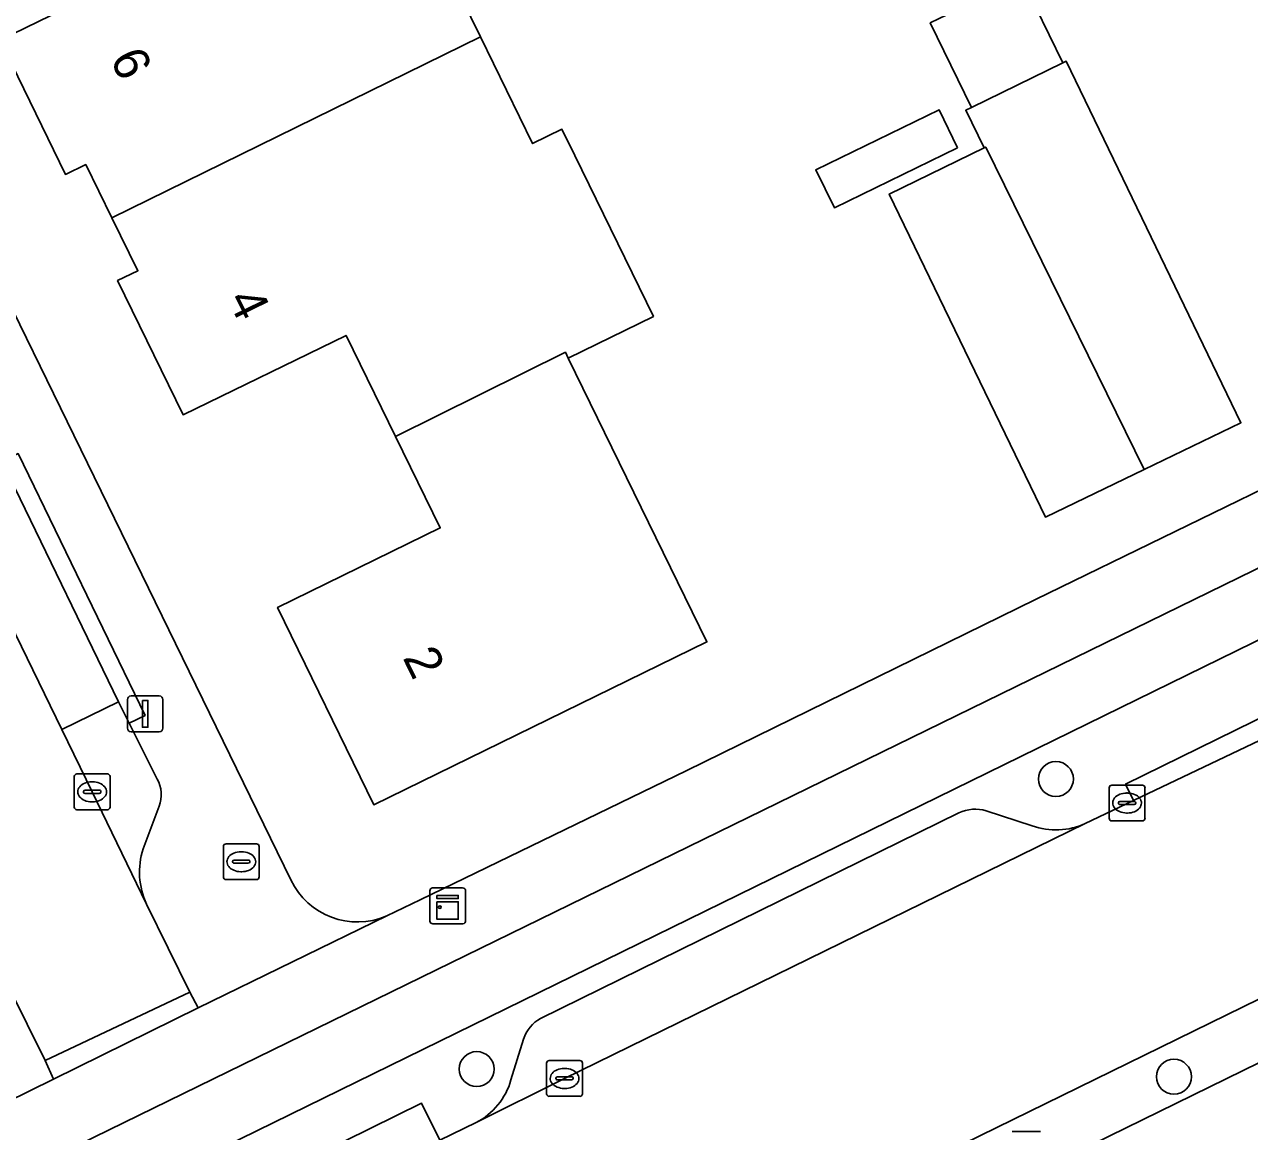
# Model space of a CAD drawing. Extents: x 160455 to 162082, y 388339 to 389736.
# Drawn here: x 160872.78 to 160907, y 388896.44 to 388927.38 of the extents above; entities that cross this region are included whole.
import ezdxf

# ---------------------------------------------------------------- set-up
doc = ezdxf.new("R2010")
doc.units = 0
for name, color, linetype in [('IMGEO_Berm_groen', 7, 'Continuous'), ('IMGEO_Boom', 7, 'Continuous'), ('IMGEO_Brandkraan', 7, 'Continuous'), ('IMGEO_Erf', 7, 'Continuous'), ('IMGEO_Fietspad_gesloten', 7, 'Continuous'), ('IMGEO_Fietspad_open', 7, 'Continuous'), ('IMGEO_Kast', 7, 'Continuous'), ('IMGEO_Kolk', 7, 'Continuous'), ('IMGEO_Lichtmast', 7, 'Continuous'), ('IMGEO_Muur', 7, 'Continuous'), ('IMGEO_Pand', 7, 'Continuous'), ('IMGEO_Pand_nummerreeks', 7, 'Continuous'), ('IMGEO_Parkeervlak_open', 7, 'Continuous'), ('IMGEO_Rijbaan_lokaal_gesloten', 7, 'Continuous'), ('IMGEO_Verkeerseiland_gesloten', 7, 'Continuous'), ('IMGEO_Verkeerseiland_open', 7, 'Continuous'), ('IMGEO_Voetpad_open', 7, 'Continuous')]:
    doc.layers.add(name, color=color, linetype=linetype)

msp = doc.modelspace()

# ---------------------------------------------------------------- linework, layer by layer
at = {"layer": 'IMGEO_Berm_groen'}
msp.add_lwpolyline([(160933.95, 388912.479), (160933.737, 388912.923), (160930.826, 388911.666), (160928.839, 388910.666), (160907.741, 388900.373), (160888.442, 388890.921), (160887.468, 388890.458), (160888.134, 388888.983), (160932.517, 388910.743)], dxfattribs=at)
at = {"layer": 'IMGEO_Boom'}
for centre in [(160901.595, 388906.294), (160885.419, 388898.187), (160904.893, 388897.975)]:
    msp.add_circle(centre, 0.489, dxfattribs=at)
at = {"layer": 'IMGEO_Brandkraan'}
for p, q in [((160878.34, 388903.558), (160878.34, 388904.41)), ((160878.415, 388904.484), (160879.267, 388904.484)), ((160879.341, 388904.41), (160879.341, 388903.558)), ((160878.642, 388904.027), (160879.04, 388904.027)), ((160878.828, 388904.264), (160878.853, 388904.264)), ((160878.599, 388903.978), (160878.599, 388903.99)), ((160879.037, 388903.941), (160878.639, 388903.941)), ((160878.851, 388903.704), (160878.826, 388903.704)), ((160879.083, 388903.99), (160879.083, 388903.978)), ((160879.267, 388903.484), (160878.415, 388903.484))]:
    msp.add_line(p, q, dxfattribs=at)
for points in [[(160878.34, 388903.558), (160878.34, 388904.41)], [(160878.415, 388904.484), (160879.267, 388904.484)], [(160879.341, 388904.41), (160879.341, 388903.558)], [(160879.267, 388903.484), (160878.415, 388903.484)]]:
    msp.add_lwpolyline(points, dxfattribs=at)
for centre, radius, start, end in [((160878.417, 388904.408), 0.0765, 91.552, 178.448), ((160878.417, 388904.408), 0.0765, 91.552, 178.448), ((160879.265, 388904.408), 0.0765, 1.552, 88.448), ((160879.265, 388904.408), 0.0765, 1.552, 88.448), ((160878.639, 388903.987), 0.0403, 85.8775, 175.7526), ((160879.044, 388903.989), 0.0386, 1.7309, 96.639), ((160878.636, 388903.977), 0.0366, 178.938, 274.7102), ((160879.04, 388903.984), 0.043, 264.8664, 352.4533), ((160878.417, 388903.56), 0.0765, 181.552, 268.448), ((160878.417, 388903.56), 0.0765, 181.552, 268.448), ((160879.265, 388903.56), 0.0765, 271.552, 358.448), ((160879.265, 388903.56), 0.0765, 271.552, 358.448)]:
    msp.add_arc(centre, radius, start, end, dxfattribs=at)
for centre, major_axis, ratio, start_param, end_param in [((160878.827, 388903.984), (-0.387, 0.002), 0.722429, 4.712389, 7.853982), ((160878.852, 388903.984), (-0.39, 0.002), 0.717154, 1.570796, 4.712389)]:
    msp.add_ellipse(centre, major_axis=major_axis, ratio=ratio, start_param=start_param, end_param=end_param, dxfattribs=at)
at = {"layer": 'IMGEO_Erf'}
for points in [[(160836.379, 388993.364), (160850.87, 388963.642), (160880.226, 388903.473)], [(160883.115, 388931.96), (160885.523, 388927.033), (160886.979, 388924.053), (160887.797, 388924.452), (160888.157, 388923.716), (160890.351, 388919.223), (160887.97, 388918.059), (160891.847, 388910.126), (160882.539, 388905.576), (160879.852, 388911.09), (160884.4, 388913.312), (160883.151, 388915.868), (160881.77, 388918.694), (160877.216, 388916.477), (160875.386, 388920.224), (160875.952, 388920.5), (160875.226, 388921.978), (160874.494, 388923.466), (160873.928, 388923.19), (160872.1, 388926.948), (160876.717, 388929.199)], [(160882.906, 388902.468), (160883.834, 388902.918), (160891.286, 388906.53), (160901.022, 388911.309), (160908.826, 388915.117), (160918.922, 388920.047), (160928.435, 388924.714)]]:
    msp.add_lwpolyline(points, dxfattribs=at)
for points in [[(160899.592, 388923.932), (160899.078, 388924.987), (160899.236, 388925.064), (160898.086, 388927.425), (160900.641, 388928.67), (160901.791, 388926.309), (160901.886, 388926.355), (160906.766, 388916.253), (160904.061, 388914.947), (160901.301, 388913.614), (160896.94, 388922.64)], [(160898.851, 388923.935), (160895.408, 388922.258), (160894.889, 388923.322), (160898.332, 388925)]]:
    msp.add_lwpolyline(points, close=True, dxfattribs=at)
msp.add_arc((160882.089, 388904.365), 2.066, 205.5909, 293.297, dxfattribs=at)
at = {"layer": 'IMGEO_Fietspad_gesloten'}
for points in [[(160935.958, 388926.245), (160935.472, 388926.041), (160929.623, 388923.115), (160929.542, 388923.081), (160924.149, 388920.448), (160820.314, 388869.678), (160812.524, 388865.895), (160804.151, 388861.828), (160752.018, 388836.29), (160739.38, 388830.051), (160696.889, 388809.242), (160688.114, 388804.953), (160688.97, 388803.215), (160707.492, 388812.318), (160716.69, 388816.833), (160716.639, 388816.936), (160723.758, 388820.418), (160723.804, 388820.325), (160740.999, 388828.766), (160761.388, 388838.743), (160804.958, 388860.084), (160820.353, 388867.581)], [(160820.353, 388867.581), (160909.887, 388911.468), (160925.131, 388918.94), (160926.09, 388919.406), (160929.273, 388920.954), (160932.035, 388922.279)]]:
    msp.add_lwpolyline(points, dxfattribs=at)
at = {"layer": 'IMGEO_Fietspad_open'}
msp.add_lwpolyline([(160936.65, 388912.778), (160936.045, 388912.477), (160933.62, 388911.27), (160933.39, 388911.155), (160932.517, 388910.743), (160888.134, 388888.983), (160875.412, 388882.733), (160870.367, 388880.302), (160868.27, 388879.237), (160861.035, 388875.725), (160851.6, 388871.082), (160844.374, 388867.53), (160835.881, 388863.365), (160828.618, 388859.824), (160821.23, 388856.204)], dxfattribs=at)
at = {"layer": 'IMGEO_Kast'}
for p, q in [((160884.108, 388902.325), (160884.108, 388903.166)), ((160884.108, 388903.166), (160884.108, 388902.325)), ((160884.183, 388903.25), (160885.024, 388903.25)), ((160885.024, 388903.25), (160884.183, 388903.25)), ((160885.108, 388903.175), (160885.108, 388902.334)), ((160885.108, 388902.334), (160885.108, 388903.175)), ((160885.033, 388902.25), (160884.192, 388902.25)), ((160884.192, 388902.25), (160885.033, 388902.25))]:
    msp.add_line(p, q, dxfattribs=at)
for points in [[(160884.303, 388903.04), (160884.903, 388903.04), (160884.903, 388902.955), (160884.303, 388902.955), (160884.303, 388903.04)], [(160884.303, 388902.865), (160884.903, 388902.865), (160884.903, 388902.376), (160884.303, 388902.376), (160884.303, 388902.865)]]:
    msp.add_lwpolyline(points, dxfattribs=at)
msp.add_circle((160884.387, 388902.714), 0.0377, dxfattribs=at)
for centre, start, end in [((160884.186, 388903.172), 92.4484, 184.2845), ((160884.186, 388903.172), 92.4484, 184.2845), ((160885.03, 388903.172), 2.4484, 94.2845), ((160885.03, 388903.172), 2.4484, 94.2845), ((160884.186, 388902.328), 182.4484, 274.2845), ((160884.186, 388902.328), 182.4484, 274.2845), ((160885.03, 388902.328), 272.4484, 4.2845), ((160885.03, 388902.328), 272.4484, 4.2845)]:
    msp.add_arc(centre, 0.0779, start, end, dxfattribs=at)
at = {"layer": 'IMGEO_Kolk'}
for p, q in [((160874.249, 388906.437), (160875.101, 388906.437)), ((160874.174, 388905.511), (160874.174, 388906.363)), ((160874.662, 388906.217), (160874.687, 388906.217)), ((160875.175, 388906.363), (160875.175, 388905.511)), ((160903.159, 388906.124), (160904.011, 388906.124)), ((160874.433, 388905.931), (160874.433, 388905.943)), ((160874.871, 388905.894), (160874.473, 388905.894)), ((160874.476, 388905.98), (160874.874, 388905.98)), ((160874.917, 388905.943), (160874.917, 388905.931)), ((160903.084, 388905.198), (160903.084, 388906.05)), ((160903.572, 388905.904), (160903.597, 388905.904)), ((160904.085, 388906.05), (160904.085, 388905.198)), ((160875.101, 388905.437), (160874.249, 388905.437)), ((160874.685, 388905.657), (160874.66, 388905.657)), ((160903.343, 388905.618), (160903.343, 388905.63)), ((160903.781, 388905.581), (160903.383, 388905.581)), ((160903.386, 388905.667), (160903.784, 388905.667)), ((160903.827, 388905.63), (160903.827, 388905.618)), ((160904.011, 388905.124), (160903.159, 388905.124)), ((160903.595, 388905.344), (160903.57, 388905.344)), ((160887.37, 388897.501), (160887.37, 388898.353)), ((160887.445, 388898.427), (160888.297, 388898.427)), ((160888.371, 388898.353), (160888.371, 388897.501)), ((160887.629, 388897.921), (160887.629, 388897.933)), ((160888.067, 388897.884), (160887.669, 388897.884)), ((160887.672, 388897.97), (160888.07, 388897.97)), ((160887.858, 388898.207), (160887.883, 388898.207)), ((160888.113, 388897.933), (160888.113, 388897.921)), ((160887.881, 388897.647), (160887.856, 388897.647)), ((160888.297, 388897.427), (160887.445, 388897.427))]:
    msp.add_line(p, q, dxfattribs=at)
for points in [[(160874.249, 388906.437), (160875.101, 388906.437)], [(160874.174, 388905.511), (160874.174, 388906.363)], [(160875.175, 388906.363), (160875.175, 388905.511)], [(160903.159, 388906.124), (160904.011, 388906.124)], [(160903.084, 388905.198), (160903.084, 388906.05)], [(160904.085, 388906.05), (160904.085, 388905.198)], [(160875.101, 388905.437), (160874.249, 388905.437)], [(160904.011, 388905.124), (160903.159, 388905.124)], [(160887.37, 388897.501), (160887.37, 388898.353)], [(160887.445, 388898.427), (160888.297, 388898.427)], [(160888.371, 388898.353), (160888.371, 388897.501)], [(160888.297, 388897.427), (160887.445, 388897.427)]]:
    msp.add_lwpolyline(points, dxfattribs=at)
for centre, radius, start, end in [((160874.251, 388906.361), 0.0765, 91.552, 178.448), ((160874.251, 388906.361), 0.0765, 91.552, 178.448), ((160875.099, 388906.361), 0.0765, 1.552, 88.448), ((160875.099, 388906.361), 0.0765, 1.552, 88.448), ((160903.161, 388906.048), 0.0765, 91.552, 178.448), ((160903.161, 388906.048), 0.0765, 91.552, 178.448), ((160904.009, 388906.048), 0.0765, 1.552, 88.448), ((160904.009, 388906.048), 0.0765, 1.552, 88.448), ((160874.473, 388905.94), 0.0403, 85.8775, 175.7526), ((160874.47, 388905.93), 0.0366, 178.938, 274.7102), ((160874.874, 388905.937), 0.043, 264.8664, 352.4533), ((160874.878, 388905.942), 0.0386, 1.7309, 96.639), ((160874.251, 388905.513), 0.0765, 181.552, 268.448), ((160874.251, 388905.513), 0.0765, 181.552, 268.448), ((160875.099, 388905.513), 0.0765, 271.552, 358.448), ((160875.099, 388905.513), 0.0765, 271.552, 358.448), ((160903.383, 388905.627), 0.0403, 85.8775, 175.7526), ((160903.38, 388905.617), 0.0366, 178.938, 274.7102), ((160903.784, 388905.624), 0.043, 264.8664, 352.4533), ((160903.788, 388905.629), 0.0386, 1.7309, 96.639), ((160903.161, 388905.2), 0.0765, 181.552, 268.448), ((160903.161, 388905.2), 0.0765, 181.552, 268.448), ((160904.009, 388905.2), 0.0765, 271.552, 358.448), ((160904.009, 388905.2), 0.0765, 271.552, 358.448), ((160887.447, 388898.351), 0.0765, 91.552, 178.448), ((160887.447, 388898.351), 0.0765, 91.552, 178.448), ((160888.295, 388898.351), 0.0765, 1.552, 88.448), ((160888.295, 388898.351), 0.0765, 1.552, 88.448), ((160887.669, 388897.93), 0.0403, 85.8775, 175.7526), ((160887.666, 388897.92), 0.0366, 178.938, 274.7102), ((160888.07, 388897.927), 0.043, 264.8664, 352.4533), ((160888.074, 388897.932), 0.0386, 1.7309, 96.639), ((160887.447, 388897.503), 0.0765, 181.552, 268.448), ((160887.447, 388897.503), 0.0765, 181.552, 268.448), ((160888.295, 388897.503), 0.0765, 271.552, 358.448), ((160888.295, 388897.503), 0.0765, 271.552, 358.448)]:
    msp.add_arc(centre, radius, start, end, dxfattribs=at)
for centre, major_axis, ratio, start_param, end_param in [((160874.661, 388905.937), (-0.387, 0.002), 0.722429, 4.712389, 7.853982), ((160874.686, 388905.937), (-0.39, 0.002), 0.717154, 1.570796, 4.712389), ((160903.571, 388905.624), (-0.387, 0.002), 0.722429, 4.712389, 7.853982), ((160903.596, 388905.624), (-0.39, 0.002), 0.717154, 1.570796, 4.712389), ((160887.857, 388897.927), (-0.387, 0.002), 0.722429, 4.712389, 7.853982), ((160887.882, 388897.927), (-0.39, 0.002), 0.717154, 1.570796, 4.712389)]:
    msp.add_ellipse(centre, major_axis=major_axis, ratio=ratio, start_param=start_param, end_param=end_param, dxfattribs=at)
at = {"layer": 'IMGEO_Lichtmast'}
for p, q in [((160875.66, 388907.716), (160875.66, 388908.516)), ((160875.66, 388908.516), (160875.66, 388907.716)), ((160875.76, 388908.616), (160876.55, 388908.616)), ((160876.55, 388908.616), (160875.76, 388908.616)), ((160876.65, 388908.516), (160876.65, 388907.716)), ((160876.65, 388907.716), (160876.65, 388908.516)), ((160876.55, 388907.616), (160875.76, 388907.616)), ((160875.76, 388907.616), (160876.55, 388907.616)), ((160900.374, 388896.444), (160901.164, 388896.444)), ((160901.164, 388896.444), (160900.374, 388896.444))]:
    msp.add_line(p, q, dxfattribs=at)
msp.add_lwpolyline([(160876.08, 388908.491), (160876.23, 388908.491), (160876.23, 388907.741), (160876.08, 388907.741), (160876.08, 388908.491)], dxfattribs=at)
for centre, start, end in [((160875.76, 388908.516), 90, 180), ((160875.76, 388908.516), 90, 180), ((160876.55, 388908.516), 0, 90), ((160876.55, 388908.516), 360, 90), ((160875.76, 388907.716), 180, 270), ((160875.76, 388907.716), 180, 270), ((160876.55, 388907.716), 270, 0), ((160876.55, 388907.716), 270, 0)]:
    msp.add_arc(centre, 0.1, start, end, dxfattribs=at)
at = {"layer": 'IMGEO_Muur'}
msp.add_lwpolyline([(160891.286, 388906.53), (160901.022, 388911.309)], dxfattribs=at)
at = {"layer": 'IMGEO_Pand'}
for points in [[(160875.226, 388921.978), (160885.523, 388927.033), (160883.115, 388931.96), (160883.933, 388932.36), (160882.398, 388935.501), (160875.346, 388932.003), (160876.717, 388929.199), (160872.1, 388926.948), (160873.928, 388923.19), (160874.494, 388923.466)], [(160900.641, 388928.67), (160898.086, 388927.425), (160899.236, 388925.064), (160901.791, 388926.309)], [(160875.226, 388921.978), (160875.952, 388920.5), (160875.386, 388920.224), (160877.216, 388916.477), (160881.77, 388918.694), (160883.151, 388915.868), (160887.896, 388918.223), (160887.97, 388918.059), (160890.351, 388919.223), (160888.157, 388923.716), (160887.797, 388924.452), (160886.979, 388924.053), (160885.523, 388927.033)], [(160901.886, 388926.355), (160901.791, 388926.309), (160899.236, 388925.064), (160899.078, 388924.987), (160899.592, 388923.932), (160899.637, 388923.954), (160904.061, 388914.947), (160906.766, 388916.253)], [(160898.851, 388923.935), (160898.332, 388925), (160894.889, 388923.322), (160895.408, 388922.258)], [(160899.592, 388923.932), (160896.94, 388922.64), (160901.301, 388913.614), (160904.061, 388914.947), (160899.637, 388923.954)], [(160887.97, 388918.059), (160887.896, 388918.223), (160883.151, 388915.868), (160884.4, 388913.312), (160879.852, 388911.09), (160882.539, 388905.576), (160891.847, 388910.126)]]:
    msp.add_lwpolyline(points, close=True, dxfattribs=at)
at = {"layer": 'IMGEO_Parkeervlak_open'}
msp.add_lwpolyline([(160872.512, 388914.437), (160870.91, 388913.656), (160873.826, 388907.675), (160875.414, 388908.45)], close=True, dxfattribs=at)
for points in [[(160876.492, 388906.293), (160875.704, 388907.852), (160875.414, 388908.45), (160873.826, 388907.675), (160874.674, 388905.936), (160876.195, 388902.798)], [(160876.096, 388904.345), (160876.546, 388905.537)], [(160900.937, 388904.985), (160899.651, 388905.405)], [(160898.886, 388905.35), (160887.203, 388899.606)], [(160885.399, 388896.691), (160887.872, 388897.926), (160902.415, 388905.053)], [(160886.723, 388899.027), (160886.374, 388897.885)]]:
    msp.add_lwpolyline(points, dxfattribs=at)
for centre, radius, start, end in [((160875.7, 388905.856), 0.904, 339.3156, 28.8557), ((160899.341, 388904.376), 1.075, 73.2169, 115.0076), ((160901.593, 388906.816), 1.945, 250.2809, 294.9875), ((160878.129, 388903.698), 2.133, 162.3535, 204.9698), ((160887.698, 388898.707), 1.026, 118.8447, 161.8368), ((160884.513, 388898.409), 1.933, 297.2658, 344.2652)]:
    msp.add_arc(centre, radius, start, end, dxfattribs=at)
at = {"layer": 'IMGEO_Rijbaan_lokaal_gesloten'}
for points in [[(160857.437, 388930.991), (160863.829, 388917.901), (160870.279, 388904.715), (160872.356, 388900.46), (160873.366, 388898.427), (160877.404, 388900.338), (160876.195, 388902.798), (160874.674, 388905.936), (160873.826, 388907.675), (160870.91, 388913.656), (160867.96, 388919.705), (160865.966, 388923.778), (160863.186, 388929.455)], [(160872.282, 388882.972), (160874.659, 388884.176), (160887.468, 388890.458), (160888.442, 388890.921), (160907.741, 388900.373), (160928.839, 388910.666), (160930.826, 388911.666), (160928.001, 388917.442), (160927.929, 388917.405), (160927.165, 388917.032), (160910.99, 388909.142), (160910.823, 388909.06), (160903.765, 388905.697), (160902.415, 388905.053), (160887.872, 388897.926), (160885.399, 388896.691), (160884.389, 388896.2), (160871.543, 388889.868)]]:
    msp.add_lwpolyline(points, dxfattribs=at)
at = {"layer": 'IMGEO_Verkeerseiland_gesloten'}
msp.add_lwpolyline([(160910.823, 388909.06), (160910.99, 388909.142), (160910.947, 388909.234), (160910.727, 388909.682), (160903.541, 388906.153), (160903.765, 388905.697)], close=True, dxfattribs=at)
at = {"layer": 'IMGEO_Verkeerseiland_open'}
for points in [[(160902.415, 388905.053), (160903.765, 388905.697), (160903.541, 388906.153), (160910.727, 388909.682), (160909.887, 388911.468), (160820.353, 388867.581), (160804.958, 388860.084), (160761.388, 388838.743), (160740.999, 388828.766), (160723.804, 388820.325), (160724.107, 388819.706), (160738.585, 388826.804), (160740.267, 388827.638)], [(160899.651, 388905.405), (160900.937, 388904.985)], [(160887.203, 388899.606), (160898.886, 388905.35)], [(160886.374, 388897.885), (160886.723, 388899.027)], [(160869.671, 388888.959), (160871.543, 388889.868), (160871.033, 388890.902), (160883.879, 388897.234), (160884.389, 388896.2), (160885.399, 388896.691)]]:
    msp.add_lwpolyline(points, dxfattribs=at)
for centre, radius, start, end in [((160899.341, 388904.376), 1.075, 73.2169, 115.0076), ((160901.593, 388906.816), 1.945, 250.2809, 294.9875), ((160887.698, 388898.707), 1.026, 118.8447, 161.8368), ((160884.513, 388898.409), 1.933, 297.2658, 344.2652)]:
    msp.add_arc(centre, radius, start, end, dxfattribs=at)
at = {"layer": 'IMGEO_Voetpad_open'}
for points in [[(160880.226, 388903.473), (160850.87, 388963.642), (160836.379, 388993.364)], [(160837.151, 388986.758), (160848.585, 388963.403), (160849.034, 388963.621), (160852.473, 388956.56), (160852.024, 388956.342), (160856.517, 388947.123), (160856.965, 388947.343), (160860.42, 388940.311), (160859.972, 388940.091), (160864.456, 388930.876), (160864.905, 388931.095), (160868.353, 388924.048), (160867.904, 388923.829), (160872.155, 388915.173), (160872.604, 388915.391), (160876.153, 388908.07), (160875.704, 388907.852), (160876.492, 388906.293)], [(160928.435, 388924.714), (160918.922, 388920.047), (160908.826, 388915.117), (160901.022, 388911.309), (160891.286, 388906.53), (160883.834, 388902.918), (160882.906, 388902.468), (160877.634, 388899.899), (160873.597, 388897.902), (160868.292, 388895.296), (160868.202, 388895.257), (160842.385, 388882.64), (160840.695, 388881.816), (160830.287, 388876.733), (160828.55, 388875.97), (160822.373, 388872.952), (160820.748, 388872.176), (160814.423, 388869.063), (160814.282, 388868.993), (160811.654, 388867.688), (160812.524, 388865.895), (160820.314, 388869.678), (160924.149, 388920.448)], [(160876.546, 388905.537), (160876.096, 388904.345)], [(160876.195, 388902.798), (160877.404, 388900.338), (160877.634, 388899.899), (160882.906, 388902.468)], [(160868.202, 388895.257), (160868.292, 388895.296), (160873.597, 388897.902), (160873.366, 388898.427), (160872.356, 388900.46)]]:
    msp.add_lwpolyline(points, dxfattribs=at)
for points in [[(160872.604, 388915.391), (160872.155, 388915.173), (160872.512, 388914.437), (160875.414, 388908.45), (160875.704, 388907.852), (160876.153, 388908.07)], [(160877.404, 388900.338), (160873.366, 388898.427), (160873.597, 388897.902), (160877.634, 388899.899)], [(160884.389, 388896.2), (160883.879, 388897.234), (160871.033, 388890.902), (160871.543, 388889.868)]]:
    msp.add_lwpolyline(points, close=True, dxfattribs=at)
for centre, radius, start, end in [((160875.7, 388905.856), 0.904, 339.3156, 28.8557), ((160878.129, 388903.698), 2.133, 162.3535, 204.9698), ((160882.089, 388904.365), 2.066, 205.5909, 293.297)]:
    msp.add_arc(centre, radius, start, end, dxfattribs=at)

# ---------------------------------------------------------------- texts
at = {"layer": 'IMGEO_Pand_nummerreeks'}
for s, rotation, p in [('6', 295.9396, (160875.16, 388926.42)), ('4', 296.0305, (160878.445, 388919.704)), ('2', 295.9802, (160883.339, 388909.686))]:
    msp.add_text(s, height=1, rotation=rotation, dxfattribs=at).set_placement(p)

doc.saveas('drawing.dxf')
